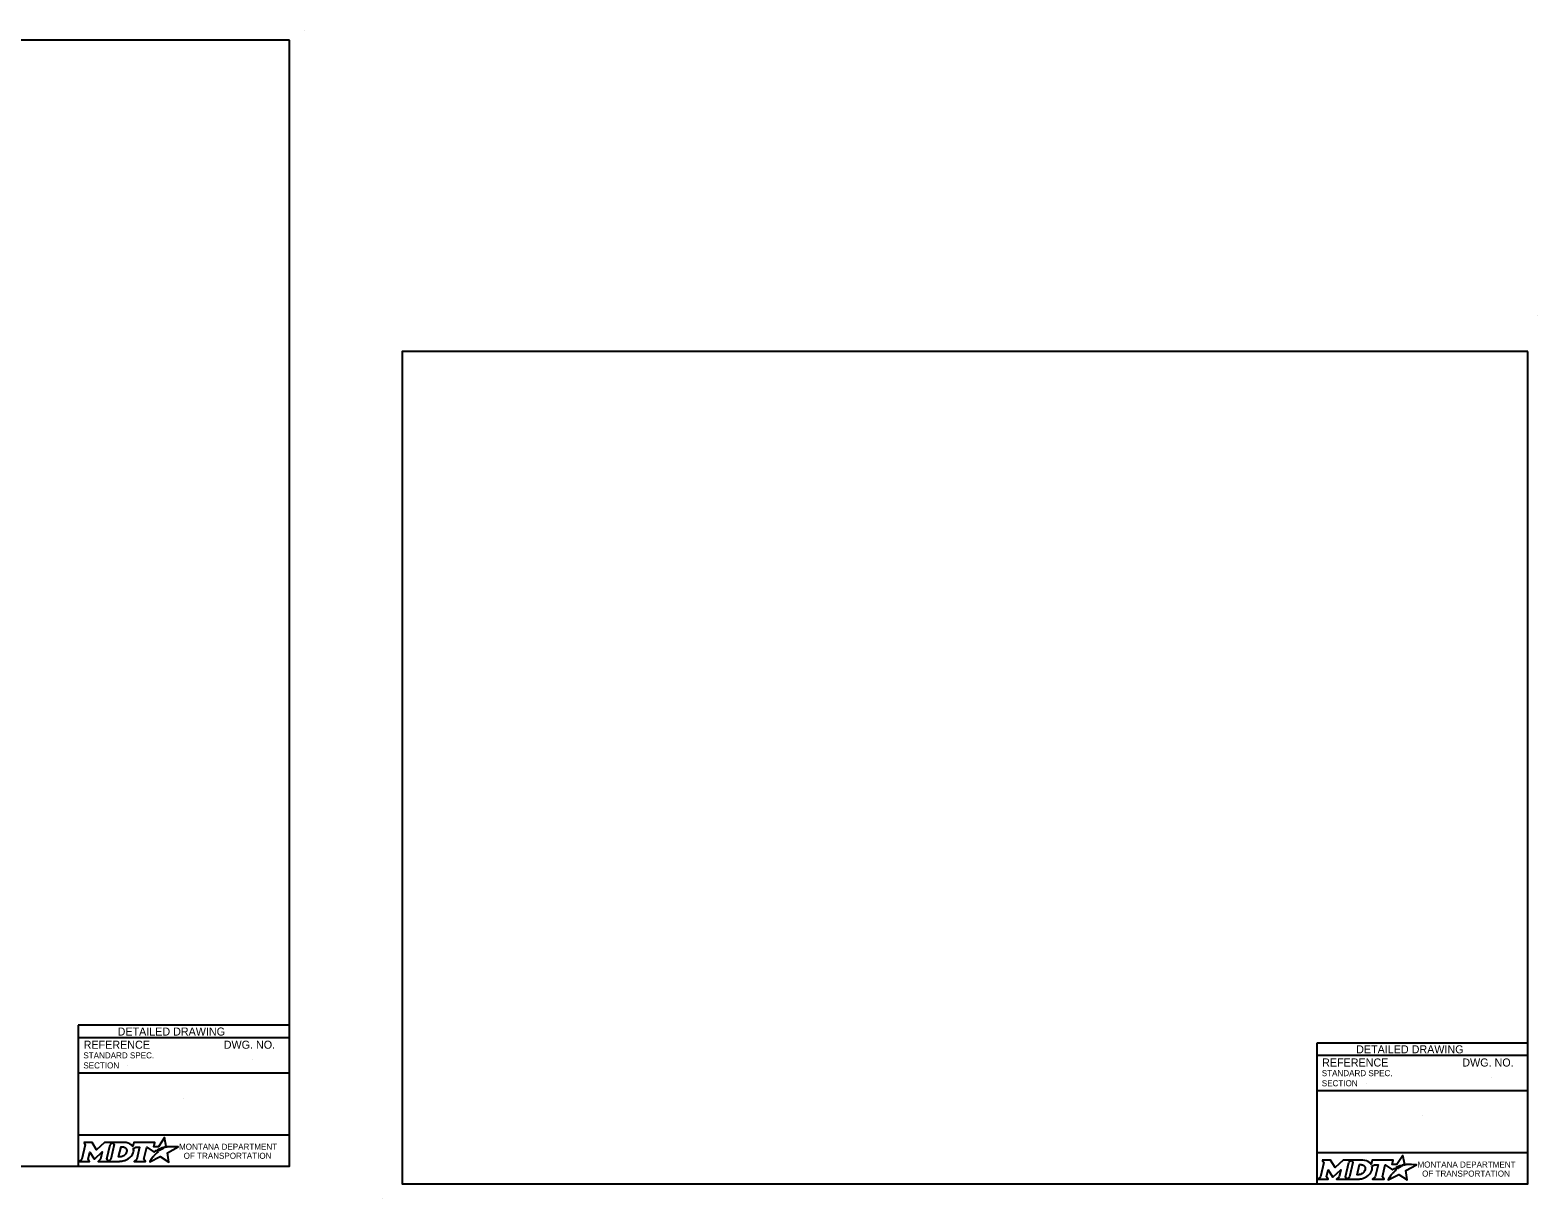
# Model space of a CAD drawing. Extents: x 49991.4 to 50021, y 49987.6 to 50011.4.
# Drawn here: x 50006.04 to 50021.04, y 49999.74 to 50011.36 of the extents above; entities that cross this region are included whole.
import ezdxf

# ---------------------------------------------------------------- set-up
doc = ezdxf.new("R2010")
doc.units = 0
for name, color, linetype in [('Default', 7, 'Continuous'), ('Level 1', 7, 'Continuous'), ('Level 2', 7, 'Continuous'), ('Level 4', 7, 'Continuous')]:
    doc.layers.add(name, color=color, linetype=linetype)

msp = doc.modelspace()

# ---------------------------------------------------------------- linework, layer by layer
at = {"layer": 'Default'}
for points in [[(50018.893, 50000.121), (50018.907, 50000.097), (50018.874, 49999.954), (50018.848, 49999.931), (50018.95, 49999.931), (50018.936, 49999.954), (50018.952, 50000.024), (50018.996, 49999.955), (50019.002, 49999.955), (50019.077, 50000.025), (50019.06, 49999.954), (50019.035, 49999.932), (50019.137, 49999.932), (50019.123, 49999.955), (50019.156, 50000.097)], [(50019.156, 50000.097), (50019.182, 50000.121), (50019.099, 50000.121), (50019.02, 50000.048), (50018.975, 50000.12), (50018.893, 50000.121)], [(50019.295, 50000.121), (50019.182, 50000.121), (50019.196, 50000.098), (50019.163, 49999.954), (50019.137, 49999.932), (50019.248, 49999.932)], [(50019.319, 50000.034), (50019.318, 50000.026), (50019.315, 50000.017), (50019.311, 50000.008), (50019.305, 50000.001), (50019.299, 49999.994), (50019.291, 49999.988), (50019.282, 49999.983), (50019.273, 49999.979), (50019.264, 49999.977), (50019.255, 49999.976), (50019.239, 49999.976), (50019.263, 50000.076), (50019.279, 50000.076), (50019.286, 50000.075), (50019.294, 50000.073), (50019.301, 50000.07), (50019.307, 50000.066), (50019.311, 50000.061), (50019.315, 50000.055), (50019.318, 50000.049), (50019.319, 50000.042), (50019.32, 50000.038), (50019.319, 50000.034)], [(50019.7, 50000.068), (50019.69, 50000.074), (50019.702, 50000.076), (50019.713, 50000.078), (50019.696, 50000.168), (50019.636, 50000.077), (50019.589, 50000.076), (50019.599, 50000.12), (50019.39, 50000.121), (50019.38, 50000.078), (50019.374, 50000.086)], [(50019.387, 50000.062), (50019.411, 50000.075), (50019.448, 50000.075), (50019.42, 49999.954), (50019.392, 49999.931), (50019.508, 49999.931), (50019.491, 49999.954), (50019.52, 50000.075), (50019.591, 50000.023), (50019.612, 50000.038), (50019.632, 50000.027)], [(50019.576, 49999.971), (50019.561, 49999.947), (50019.556, 49999.939), (50019.55, 49999.931), (50019.548, 49999.926), (50019.653, 49999.979), (50019.737, 49999.924), (50019.724, 50000.017), (50019.831, 50000.075), (50019.782, 50000.076), (50019.751, 50000.077), (50019.731, 50000.077), (50019.724, 50000.075), (50019.719, 50000.074), (50019.711, 50000.072), (50019.7, 50000.068)], [(50019.65, 50000.04), (50019.648, 50000.039), (50019.629, 50000.048), (50019.639, 50000.054), (50019.644, 50000.056), (50019.652, 50000.06), (50019.658, 50000.063), (50019.666, 50000.066), (50019.673, 50000.068), (50019.685, 50000.061), (50019.681, 50000.059), (50019.676, 50000.056), (50019.672, 50000.054), (50019.667, 50000.051), (50019.665, 50000.05), (50019.662, 50000.049), (50019.66, 50000.047), (50019.658, 50000.046), (50019.655, 50000.044), (50019.652, 50000.042), (50019.65, 50000.04)], [(50019.293, 49999.939), (50019.302, 49999.942), (50019.315, 49999.947), (50019.335, 49999.958)], [(50019.59, 49999.987), (50019.59, 49999.987)]]:
    msp.add_lwpolyline(points, dxfattribs=at)
for centre, radius, start, end in [((50019.319, 50000.042), 0.0709, 339.5329, 15.8582), ((50019.274, 50000.059), 0.118, 300.9103, 339.1383)]:
    msp.add_arc(centre, radius, start, end, dxfattribs=at)
for centre, major_axis, ratio, start_param, end_param in [((50019.293, 50000.073), (0.0834, -0.0037), 0.568097, 0.61298, 1.570796), ((50019.349, 50000.081), (0.0361, -0.0295), 0.469099, 1.225588, 1.570796), ((50019.621, 50000.017), (-0.0112, -0.0097), 0.021651, 3.157348, 6.283185), ((50019.248, 50000.08), (0, 0.148), 0.987302, 3.139398, 3.456847), ((50019.583, 49999.979), (-0.00694, -0.00806), 0.008222, 0, 3.137361), ((50019.6, 49999.997), (-0.0098, -0.0102), 0.016458, 3.141593, 6.279097)]:
    msp.add_ellipse(centre, major_axis=major_axis, ratio=ratio, start_param=start_param, end_param=end_param, dxfattribs=at)
at = {"layer": 'Level 1'}
for p, q in [((50008.765, 50011.363), (50008.765, 50011.363)), ((50021.038, 50008.524), (50021.038, 50008.524)), ((50009.537, 49999.736), (50009.537, 49999.736))]:
    msp.add_line(p, q, dxfattribs=at)
for points in [[(50008.615, 50011.263), (50000.336, 50011.263), (50000.336, 50000.062), (50008.615, 50000.062)], [(50020.938, 50008.165), (50009.737, 50008.165), (50009.737, 49999.886), (50020.938, 49999.886)]]:
    msp.add_lwpolyline(points, close=True, dxfattribs=at)
at = {"layer": 'Level 2'}
for p, q in [((50008.615, 50001.462), (50006.515, 50001.462)), ((50006.515, 50001.462), (50006.515, 50000.062)), ((50008.615, 50001.337), (50006.515, 50001.337)), ((50008.251, 50001.122), (50008.251, 50001.122)), ((50008.615, 50000.987), (50006.515, 50000.987)), ((50007.009, 50001.063), (50007.009, 50001.063)), ((50007.565, 50000.738), (50007.565, 50000.738)), ((50008.615, 50000.369), (50006.515, 50000.369))]:
    msp.add_line(p, q, dxfattribs=at)
for points in [[(50007.377, 50000.245), (50007.367, 50000.25), (50007.378, 50000.253), (50007.39, 50000.255), (50007.373, 50000.345), (50007.313, 50000.254), (50007.266, 50000.253), (50007.276, 50000.297), (50007.067, 50000.297), (50007.057, 50000.255), (50007.051, 50000.263)], [(50006.57, 50000.297), (50006.584, 50000.274), (50006.551, 50000.131), (50006.525, 50000.108), (50006.627, 50000.108), (50006.613, 50000.131), (50006.629, 50000.201), (50006.673, 50000.132), (50006.678, 50000.132), (50006.753, 50000.202), (50006.737, 50000.13), (50006.712, 50000.108), (50006.814, 50000.108), (50006.8, 50000.132), (50006.833, 50000.274)], [(50006.833, 50000.274), (50006.859, 50000.297), (50006.776, 50000.297), (50006.697, 50000.224), (50006.652, 50000.297), (50006.57, 50000.297)], [(50006.972, 50000.297), (50006.859, 50000.297), (50006.873, 50000.275), (50006.839, 50000.131), (50006.814, 50000.108), (50006.925, 50000.108)], [(50006.996, 50000.211), (50006.995, 50000.203), (50006.992, 50000.193), (50006.988, 50000.185), (50006.982, 50000.178), (50006.976, 50000.171), (50006.968, 50000.164), (50006.959, 50000.16), (50006.95, 50000.156), (50006.941, 50000.154), (50006.932, 50000.153), (50006.916, 50000.153), (50006.94, 50000.253), (50006.956, 50000.253), (50006.963, 50000.252), (50006.971, 50000.25), (50006.977, 50000.247), (50006.983, 50000.243), (50006.988, 50000.238), (50006.992, 50000.232), (50006.995, 50000.226), (50006.996, 50000.218), (50006.996, 50000.215), (50006.996, 50000.211)], [(50007.064, 50000.238), (50007.088, 50000.251), (50007.125, 50000.251), (50007.097, 50000.131), (50007.069, 50000.108), (50007.185, 50000.108), (50007.168, 50000.131), (50007.196, 50000.251), (50007.268, 50000.2), (50007.289, 50000.215), (50007.309, 50000.204)], [(50007.253, 50000.148), (50007.237, 50000.124), (50007.233, 50000.116), (50007.227, 50000.107), (50007.225, 50000.103), (50007.33, 50000.156), (50007.414, 50000.101), (50007.401, 50000.194), (50007.508, 50000.252), (50007.458, 50000.253), (50007.428, 50000.253), (50007.407, 50000.254), (50007.401, 50000.252), (50007.396, 50000.251), (50007.387, 50000.249), (50007.377, 50000.245)], [(50007.327, 50000.217), (50007.324, 50000.215), (50007.306, 50000.225), (50007.316, 50000.231), (50007.32, 50000.233), (50007.329, 50000.237), (50007.335, 50000.239), (50007.343, 50000.243), (50007.35, 50000.245), (50007.362, 50000.238), (50007.358, 50000.236), (50007.353, 50000.233), (50007.349, 50000.231), (50007.344, 50000.228), (50007.342, 50000.227), (50007.339, 50000.225), (50007.337, 50000.224), (50007.334, 50000.222), (50007.332, 50000.221), (50007.329, 50000.219), (50007.327, 50000.217)], [(50006.97, 50000.116), (50006.979, 50000.118), (50006.992, 50000.124), (50007.012, 50000.135)], [(50007.267, 50000.164), (50007.267, 50000.164)]]:
    msp.add_lwpolyline(points, dxfattribs=at)
for centre, radius, start, end in [((50006.951, 50000.236), 0.118, 300.9103, 339.1383), ((50006.995, 50000.219), 0.0709, 339.5329, 15.8582)]:
    msp.add_arc(centre, radius, start, end, dxfattribs=at)
for centre, major_axis, ratio, start_param, end_param in [((50006.97, 50000.25), (0.0834, -0.0037), 0.568097, 0.61298, 1.570796), ((50007.026, 50000.257), (0.0361, -0.0295), 0.469099, 1.225588, 1.570796), ((50007.276, 50000.174), (-0.0098, -0.0102), 0.016458, 3.141593, 6.279097), ((50007.297, 50000.194), (-0.0112, -0.0097), 0.021651, 3.157348, 6.283185), ((50006.925, 50000.257), (0, 0.148), 0.987302, 3.139398, 3.456847), ((50007.26, 50000.156), (-0.00694, -0.00806), 0.008222, 0, 3.137361)]:
    msp.add_ellipse(centre, major_axis=major_axis, ratio=ratio, start_param=start_param, end_param=end_param, dxfattribs=at)
at = {"layer": 'Level 4'}
for p, q in [((50020.938, 50001.286), (50018.838, 50001.286)), ((50018.838, 50001.286), (50018.838, 49999.886)), ((50020.938, 50001.161), (50018.838, 50001.161)), ((50020.574, 50000.946), (50020.574, 50000.946)), ((50020.938, 50000.811), (50018.838, 50000.811)), ((50019.332, 50000.886), (50019.332, 50000.886)), ((50019.888, 50000.562), (50019.888, 50000.562)), ((50020.938, 50000.193), (50018.838, 50000.193))]:
    msp.add_line(p, q, dxfattribs=at)

# ---------------------------------------------------------------- texts
at = {"layer": 'Default'}
for s, p in [('MONTANA DEPARTMENT', (50019.84, 50000.047)), ('OF TRANSPORTATION', (50019.886, 49999.957))]:
    msp.add_text(s, height=0.06, rotation=360, dxfattribs=at).set_placement(p)
at = {"layer": 'Level 2'}
for s, height, p in [('DETAILED DRAWING', 0.0799, (50006.906, 50001.36)), ('REFERENCE', 0.08, (50006.568, 50001.229)), ('DWG. NO.', 0.08, (50007.962, 50001.229)), ('STANDARD SPEC.', 0.06, (50006.565, 50001.133)), ('SECTION', 0.06, (50006.565, 50001.033))]:
    msp.add_text(s, height=height, dxfattribs=at).set_placement(p)
for s, p in [('MONTANA DEPARTMENT', (50007.517, 50000.224)), ('OF TRANSPORTATION', (50007.563, 50000.134))]:
    msp.add_text(s, height=0.06, rotation=360, dxfattribs=at).set_placement(p)
at = {"layer": 'Level 4'}
for s, height, p in [('DETAILED DRAWING', 0.0799, (50019.23, 50001.183)), ('REFERENCE', 0.08, (50018.891, 50001.052)), ('DWG. NO.', 0.08, (50020.286, 50001.052)), ('STANDARD SPEC.', 0.06, (50018.888, 50000.956)), ('SECTION', 0.06, (50018.888, 50000.856))]:
    msp.add_text(s, height=height, dxfattribs=at).set_placement(p)

doc.saveas('drawing.dxf')
